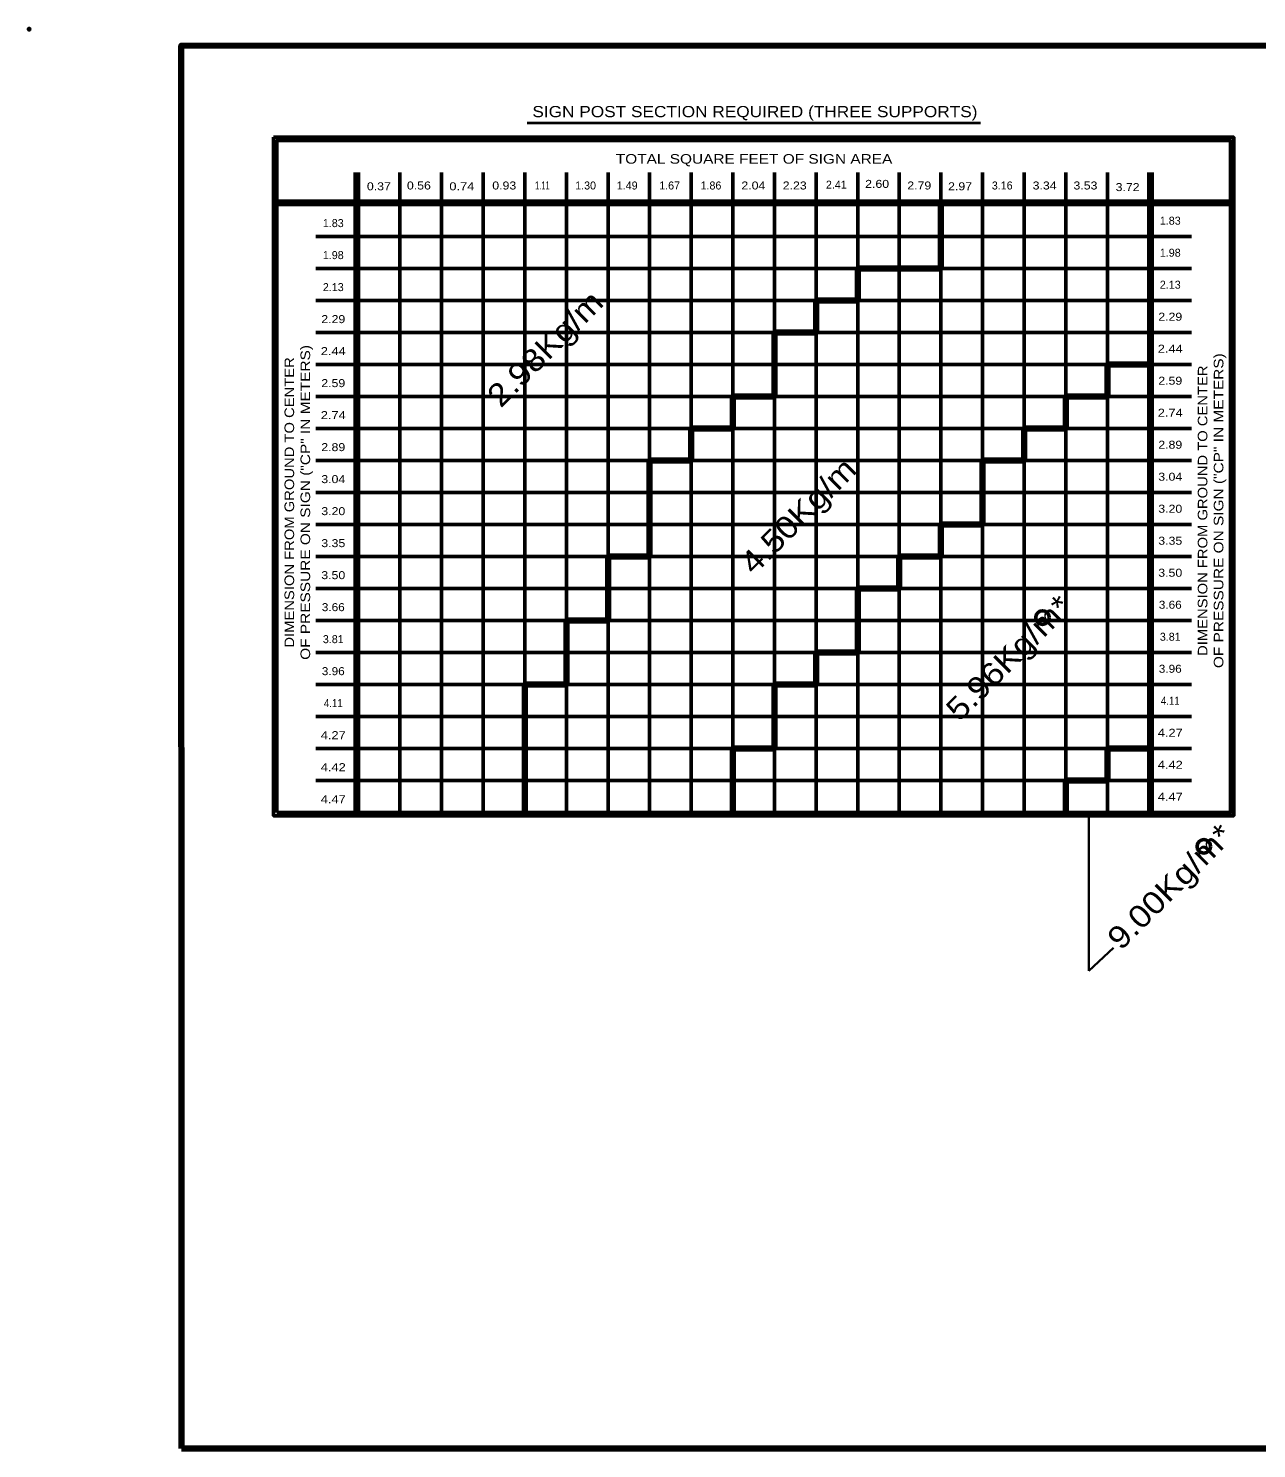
# Model space of a CAD drawing. Extents: x -35 to 678, y -12 to 441.
# Drawn here: x -34.7 to 349.1, y -2.6 to 441.2 of the extents above; entities that cross this region are included whole.
import ezdxf
from ezdxf.enums import TextEntityAlignment as Align

# ---------------------------------------------------------------- set-up
doc = ezdxf.new("R2010")
doc.units = 0
doc.header["$PDMODE"] = 32
doc.header["$PDSIZE"] = 0.5
doc.layers.add('1', color=7, linetype='Continuous', lineweight=53)

msp = doc.modelspace()

# ---------------------------------------------------------------- linework, layer by layer
at = {"layer": '1', "lineweight": 40}
msp.add_line((121.189, 411.615), (262.807, 411.615), dxfattribs=at)
at = {"layer": '1'}
for p, q in [((67.426, 196.137), (67.426, 396.137)), ((68.426, 196.137), (68.426, 396.137)), ((94.426, 196.137), (94.426, 396.137)), ((107.426, 196.137), (107.426, 396.137)), ((120.426, 236.137), (120.426, 396.137)), ((133.426, 256.137), (133.426, 396.137)), ((146.426, 276.137), (146.426, 396.137)), ((159.426, 306.137), (159.426, 396.137)), ((172.426, 316.137), (172.426, 396.137)), ((185.426, 326.137), (185.426, 396.137)), ((198.426, 346.137), (198.426, 396.137)), ((211.426, 356.137), (211.426, 396.137)), ((224.426, 366.137), (224.426, 396.137)), ((237.426, 276.137), (237.426, 396.137)), ((250.426, 386.137), (250.426, 396.137)), ((263.426, 306.137), (263.426, 396.137)), ((276.426, 316.137), (276.426, 396.137)), ((289.426, 326.137), (289.426, 396.137)), ((302.426, 336.137), (302.426, 396.137)), ((315.426, 396.137), (315.426, 196.137)), ((316.426, 396.137), (316.426, 196.137)), ((42.926, 387.137), (340.926, 387.137)), ((42.926, 386.137), (340.926, 386.137)), ((55.176, 376.137), (67.426, 376.137)), ((68.426, 376.137), (316.426, 376.137)), ((316.426, 376.137), (328.676, 376.137)), ((55.176, 366.137), (224.426, 366.137)), ((250.426, 366.137), (328.676, 366.137)), ((250.426, 286.137), (250.426, 366.137)), ((55.176, 356.137), (211.426, 356.137)), ((224.426, 356.137), (328.676, 356.137)), ((224.426, 266.137), (224.426, 356.137)), ((55.176, 346.137), (198.426, 346.137)), ((211.426, 346.137), (328.676, 346.137)), ((211.426, 246.137), (211.426, 346.137)), ((55.176, 336.137), (302.426, 336.137)), ((315.426, 336.137), (328.676, 336.137)), ((55.176, 326.137), (185.426, 326.137)), ((198.426, 236.137), (198.426, 326.137)), ((198.426, 326.137), (289.426, 326.137)), ((302.426, 326.137), (328.676, 326.137)), ((302.426, 216.137), (302.426, 326.137)), ((55.176, 316.137), (172.426, 316.137)), ((185.426, 216.137), (185.426, 316.137)), ((185.426, 316.137), (276.426, 316.137)), ((289.426, 316.137), (328.676, 316.137)), ((289.426, 206.137), (289.426, 316.137)), ((55.176, 306.137), (159.426, 306.137)), ((172.426, 196.137), (172.426, 306.137)), ((172.426, 306.137), (263.426, 306.137)), ((276.426, 306.137), (328.676, 306.137)), ((276.426, 196.137), (276.426, 306.137)), ((55.176, 296.137), (328.676, 296.137)), ((55.176, 286.137), (250.426, 286.137)), ((263.426, 286.137), (328.676, 286.137)), ((263.426, 196.137), (263.426, 286.137)), ((55.176, 276.137), (146.426, 276.137)), ((159.426, 196.137), (159.426, 276.137)), ((159.426, 276.137), (237.426, 276.137)), ((250.426, 276.137), (328.676, 276.137)), ((250.426, 196.137), (250.426, 276.137)), ((55.176, 266.137), (224.426, 266.137)), ((237.426, 266.137), (328.676, 266.137)), ((237.426, 196.137), (237.426, 266.137)), ((55.176, 256.137), (133.426, 256.137)), ((146.426, 256.137), (328.676, 256.137)), ((146.426, 196.137), (146.426, 256.137)), ((55.176, 246.137), (211.426, 246.137)), ((224.426, 246.137), (328.676, 246.137)), ((224.426, 196.137), (224.426, 246.137)), ((55.176, 236.137), (120.426, 236.137)), ((133.426, 196.137), (133.426, 236.137)), ((133.426, 236.137), (198.426, 236.137)), ((211.426, 236.137), (328.676, 236.137)), ((211.426, 196.137), (211.426, 236.137)), ((55.176, 226.137), (328.676, 226.137)), ((55.176, 216.137), (185.426, 216.137)), ((198.426, 196.137), (198.426, 216.137)), ((198.426, 216.137), (302.426, 216.137)), ((315.426, 216.137), (328.676, 216.137)), ((55.176, 206.137), (289.426, 206.137)), ((302.426, 206.137), (328.676, 206.137)), ((302.426, 196.137), (302.426, 206.137))]:
    msp.add_line(p, q, dxfattribs=at)
at = {"layer": '1', "lineweight": 200}
for p, q in [((250.426, 366.137), (250.426, 386.137)), ((224.426, 356.137), (224.426, 366.137)), ((224.426, 366.137), (250.426, 366.137)), ((211.426, 346.137), (211.426, 356.137)), ((211.426, 356.137), (224.426, 356.137)), ((198.426, 326.137), (198.426, 346.137)), ((198.426, 346.137), (211.426, 346.137)), ((302.426, 326.137), (302.426, 336.137)), ((302.426, 336.137), (315.426, 336.137)), ((185.426, 316.137), (185.426, 326.137)), ((185.426, 326.137), (198.426, 326.137)), ((289.426, 316.137), (289.426, 326.137)), ((289.426, 326.137), (302.426, 326.137)), ((172.426, 306.137), (172.426, 316.137)), ((172.426, 316.137), (185.426, 316.137)), ((276.426, 306.137), (276.426, 316.137)), ((276.426, 316.137), (289.426, 316.137)), ((159.426, 276.137), (159.426, 306.137)), ((159.426, 306.137), (172.426, 306.137)), ((263.426, 286.137), (263.426, 306.137)), ((263.426, 306.137), (276.426, 306.137)), ((250.426, 276.137), (250.426, 286.137)), ((250.426, 286.137), (263.426, 286.137)), ((146.426, 256.137), (146.426, 276.137)), ((146.426, 276.137), (159.426, 276.137)), ((237.426, 266.137), (237.426, 276.137)), ((237.426, 276.137), (250.426, 276.137)), ((224.426, 246.137), (224.426, 266.137)), ((224.426, 266.137), (237.426, 266.137)), ((133.426, 236.137), (133.426, 256.137)), ((133.426, 256.137), (146.426, 256.137)), ((211.426, 236.137), (211.426, 246.137)), ((211.426, 246.137), (224.426, 246.137)), ((120.426, 196.137), (120.426, 236.137)), ((120.426, 236.137), (133.426, 236.137)), ((198.426, 216.137), (198.426, 236.137)), ((198.426, 236.137), (211.426, 236.137)), ((185.426, 196.137), (185.426, 216.137)), ((185.426, 216.137), (198.426, 216.137)), ((302.426, 206.137), (302.426, 216.137)), ((302.426, 216.137), (315.426, 216.137)), ((289.426, 196.137), (289.426, 206.137)), ((289.426, 206.137), (302.426, 206.137))]:
    msp.add_line(p, q, dxfattribs=at)
at = {"layer": '1', "lineweight": 35}
for p in [(296.667, 196.137), (304.333, 153.917)]:
    msp.add_line(p, (296.667, 146.741), dxfattribs=at)
at = {"layer": '1', "lineweight": 158}
msp.add_line((672.833, -2.583), (13.167, -2.583), dxfattribs=at)
msp.add_lwpolyline([(672.833, 435.833), (13.083, 435.75), (13.167, -2.583)], dxfattribs=at)
at = {"layer": '1'}
for points in [[(41.926, 407.137), (341.926, 407.137), (341.926, 195.137), (41.926, 195.137)], [(42.926, 196.137), (42.926, 406.137), (340.926, 406.137), (340.926, 196.137)]]:
    msp.add_lwpolyline(points, close=True, dxfattribs=at)
msp.add_lwpolyline([(81.426, 196.137), (81.426, 386.137), (81.426, 396.137)], dxfattribs=at)
for centre, radius in [((282.167, 257.083), 2.125), ((332.583, 185.583), 2.103)]:
    msp.add_circle(centre, radius, dxfattribs=at)
msp.add_point((-34.417, 440.917), dxfattribs=at)

# ---------------------------------------------------------------- texts
for s, height, width, p in [('SIGN POST SECTION REQUIRED (THREE SUPPORTS)', 3.5, 1.15, (192.323, 413.422)), ('TOTAL SQUARE FEET OF SIGN AREA', 3, 1.2, (192.049, 398.894)), ('0.37', 2.5, 1.15, (74.833, 390.583)), ('0.56', 2.5, 1.15, (87.333, 390.833)), ('0.74', 2.5, 1.2, (100.75, 390.583)), ('0.93', 2.5, 1.15, (114, 390.833)), ('1.11', 2.5, 0.7, (125.917, 390.833)), ('2.04', 2.5, 1.15, (191.833, 390.833)), ('2.23', 2.5, 1.15, (204.75, 390.833)), ('2.60', 2.5, 1.15, (230.5, 391.333)), ('2.79', 2.5, 1.15, (243.667, 390.833)), ('2.97', 2.5, 1.15, (256.417, 390.583)), ('3.34', 2.5, 1.15, (282.833, 390.833)), ('3.53', 2.5, 1.15, (295.583, 390.833)), ('3.72', 2.5, 1.15, (308.75, 390.333)), ('2.29', 2.5, 1.15, (60.583, 349.083)), ('2.29', 2.5, 1.15, (322.083, 349.833)), ('2.44', 2.5, 1.2, (322.083, 339.833)), ('2.44', 2.5, 1.2, (60.583, 339.083)), ('2.59', 2.5, 1.15, (60.583, 329.083)), ('2.59', 2.5, 1.15, (322.083, 329.833)), ('2.74', 2.5, 1.2, (60.583, 319.083)), ('2.74', 2.5, 1.2, (322.083, 319.833)), ('2.89', 2.5, 1.15, (60.583, 309.083)), ('2.89', 2.5, 1.15, (322.083, 309.833)), ('3.04', 2.5, 1.15, (322.083, 299.833)), ('3.04', 2.5, 1.15, (60.583, 299.083)), ('3.20', 2.5, 1.15, (60.583, 289.083)), ('3.20', 2.5, 1.15, (322.083, 289.833)), ('3.35', 2.5, 1.15, (60.583, 279.083)), ('3.35', 2.5, 1.15, (322.083, 279.833)), ('3.50', 2.5, 1.15, (60.583, 269.083)), ('3.50', 2.5, 1.15, (322.083, 269.833)), ('3.66', 2.5, 1.1, (322.083, 259.833)), ('3.66', 2.5, 1.1, (60.583, 259.083)), ('3.96', 2.5, 1.1, (60.583, 239.083)), ('3.96', 2.5, 1.1, (322.083, 239.833)), ('4.11', 2.5, 0.9, (60.583, 229.083)), ('4.11', 2.5, 0.9, (322.083, 229.833)), ('4.27', 2.5, 1.2, (322.083, 219.833)), ('4.27', 2.5, 1.2, (60.583, 219.083)), ('4.42', 2.5, 1.2, (60.583, 209.083)), ('4.42', 2.5, 1.2, (322.083, 209.833)), ('4.47', 2.5, 1.2, (60.583, 199.083)), ('4.47', 2.5, 1.2, (322.083, 199.833))]:
    msp.add_text(s, height=height, dxfattribs=dict(at, width=width)).set_placement(p, align=Align.CENTER)
for s, p in [('1.30', (139.417, 390.833)), ('1.49', (152.417, 390.833)), ('1.67', (165.667, 390.833)), ('1.86', (178.583, 390.833)), ('2.41', (217.75, 391.083)), ('3.16', (269.583, 390.833)), ('1.83', (322.083, 379.833)), ('1.83', (60.583, 379.083)), ('1.98', (60.583, 369.083)), ('1.98', (322.083, 369.833)), ('2.13', (60.583, 359.083)), ('2.13', (322.083, 359.833)), ('3.81', (60.583, 249.083)), ('3.81', (322.083, 249.833))]:
    msp.add_text(s, height=2.5, dxfattribs=at).set_placement(p, align=Align.CENTER)
for s, height, rotation, width, p in [('2.98Kg/m', 7, 45, 1.15, (129.217, 338.655)), ('OF PRESSURE ON SIGN ("CP" IN METERS)', 3, 90, 1.2, (53.352, 293.055)), ('DIMENSION FROM GROUND TO CENTER', 3, 90, 1.15, (48.352, 293.055)), ('OF PRESSURE ON SIGN ("CP" IN METERS)', 3, 90, 1.2, (338.685, 290.472)), ('DIMENSION FROM GROUND TO CENTER', 3, 90, 1.15, (333.685, 290.472)), ('4.50Kg/m', 7, 45, 1.15, (208.31, 286.411)), ('5.96Kg/m*', 7, 45, 1.15, (274.033, 242.083)), ('9.00Kg/m*', 7, 45, 1.15, (324.45, 170.583))]:
    msp.add_text(s, height=height, rotation=rotation, dxfattribs=dict(at, width=width)).set_placement(p, align=Align.CENTER)

doc.saveas('drawing.dxf')
